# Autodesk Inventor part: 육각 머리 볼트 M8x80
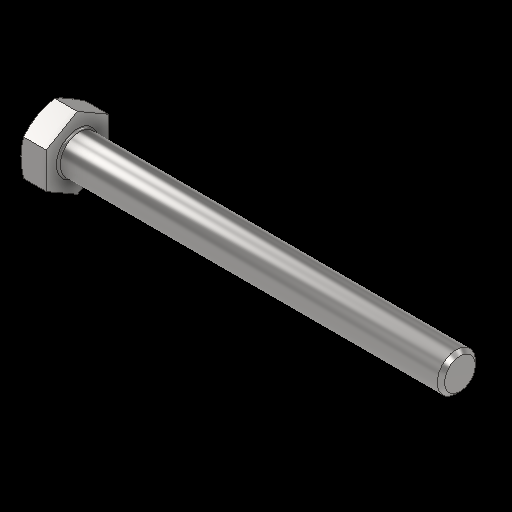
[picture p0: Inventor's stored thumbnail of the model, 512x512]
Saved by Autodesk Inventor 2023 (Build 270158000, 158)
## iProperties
Created: 2025-01
Part Number: 육각 머리 볼트 M8x80
Material: 강철, 연강
Description: 6각 머리 볼트 및 6각 머리 나사
Document SubType Name: Modeling
Designer: 강의실01
Density: 7.85 g/cm^3
Appearance: 기본값
Author: jhkim
Sending System: Autodesk Inventor 2025
Preprocessor: ST-DEVELOPER v20
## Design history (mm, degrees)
feature "Solid1"
node "솔리드1"
